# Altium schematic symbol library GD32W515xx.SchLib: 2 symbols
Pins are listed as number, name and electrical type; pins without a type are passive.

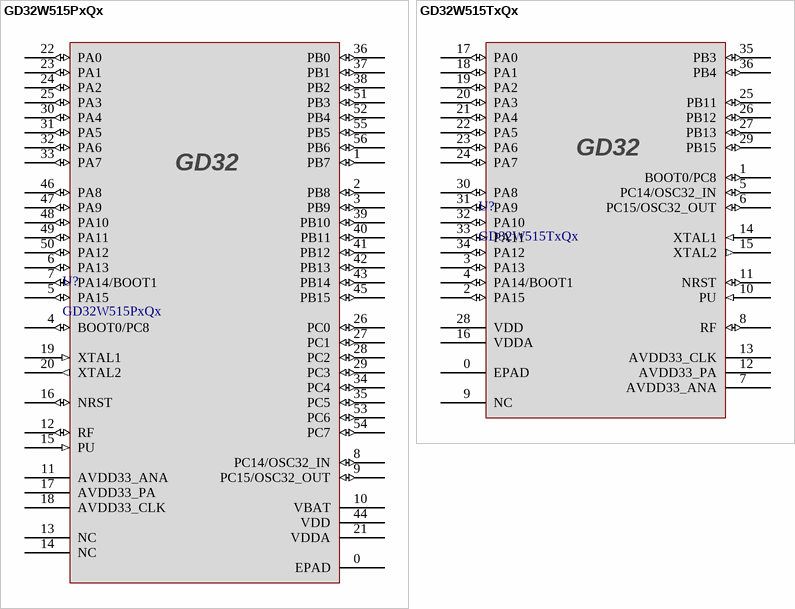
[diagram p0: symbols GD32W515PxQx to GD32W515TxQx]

## GD32W515PxQx
designator U?
footprint QFN56_7X7X0.8
pins: 0 EPAD (power), 1 PB7 (io), 2 PB8 (io), 3 PB9 (io), 4 BOOT0/PC8 (io), 5 PA15 (io), 6 PA13 (io), 7 PA14/BOOT1 (io), 8 PC14/OSC32_IN (io), 9 PC15/OSC32_OUT (io), 10 VBAT (power), 11 AVDD33_ANA (power), 12 RF (io), 13 NC, 14 NC, 15 PU (in), 16 NRST (io), 17 AVDD33_PA (power), 18 AVDD33_CLK (power), 19 XTAL1 (in), 20 XTAL2 (out), 21 VDDA (power), 22 PA0 (io), 23 PA1 (io), 24 PA2 (io), 25 PA3 (io), 26 PC0 (io), 27 PC1 (io), 28 PC2 (io), 29 PC3 (io), 30 PA4 (io), 31 PA5 (io), 32 PA6 (io), 33 PA7 (io), 34 PC4 (io), 35 PC5 (io), 36 PB0 (io), 37 PB1 (io), 38 PB2 (io), 39 PB10 (io), 40 PB11 (io), 41 PB12 (io), 42 PB13 (io), 43 PB14 (io), 44 VDD (power), 45 PB15 (io), 46 PA8 (io), 47 PA9 (io), 48 PA10 (io), 49 PA11 (io), 50 PA12 (io), 51 PB3 (io), 52 PB4 (io), 53 PC6 (io), 54 PC7 (io), 55 PB5 (io), 56 PB6 (io)

## GD32W515TxQx
designator U?
footprint QFN36_5X5X0.8
pins: 0 EPAD (power), 1 BOOT0/PC8 (io), 2 PA15 (io), 3 PA13 (io), 4 PA14/BOOT1 (io), 5 PC14/OSC32_IN (io), 6 PC15/OSC32_OUT (io), 7 AVDD33_ANA, 8 RF (io), 9 NC, 10 PU (in), 11 NRST (io), 12 AVDD33_PA, 13 AVDD33_CLK, 14 XTAL1 (in), 15 XTAL2 (out), 16 VDDA (power), 17 PA0 (io), 18 PA1 (io), 19 PA2 (io), 20 PA3 (io), 21 PA4 (io), 22 PA5 (io), 23 PA6 (io), 24 PA7 (io), 25 PB11 (io), 26 PB12 (io), 27 PB13 (io), 28 VDD (power), 29 PB15 (io), 30 PA8 (io), 31 PA9 (io), 32 PA10 (io), 33 PA11 (io), 34 PA12 (io), 35 PB3 (io), 36 PB4 (io)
